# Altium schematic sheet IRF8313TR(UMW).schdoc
size 127 x 101 mm
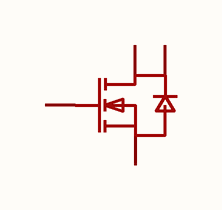
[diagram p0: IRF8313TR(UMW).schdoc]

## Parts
Q?  irf8313tr(umw)  [SOP-8_L4.9-W3.9-P1.27-LS6.0-BL]  (value not drawn)  (part A of 2)

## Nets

Not connected (* = marked no-connect by the designer): Q? 1(S1) 2(G1) 7(D1) 8(D1)

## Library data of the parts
Q? = irf8313tr(umw): 数量:2个N沟道;漏源电压(Vdss):30V;连续漏极电流(Id):9A;导通电阻(RDS(on)):18mΩ@4.5V;耗散功率(Pd):1.6W;阈值电压(Vgs(th)):2.5V;; Manufacturer: UMW(友台半导体); AddInBom: yes; ModelId: 75c24a7891ee4dd6bdac16a7163ff87e; ModelName: SOP-8_L4.9-W3.9-P1.27-LS6.0-BL-1; ModelTransform: 192.913,236.22,0,0,0,0,-0.393,2.749,0; Number: 2个N沟道; Drain to Source Voltage: 30V; Current - Continuous Drain(Id): 9A; Pd - Power Dissipation: 1.6W; Gate Threshold Voltage (Vgs(th)): 2.5V; Gate Charge(Qg): 5.3nC@4.5V; Input Capacitance(Ciss): 580pF; Reverse Transfer Capacitance (Crss@Vds): 39pF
